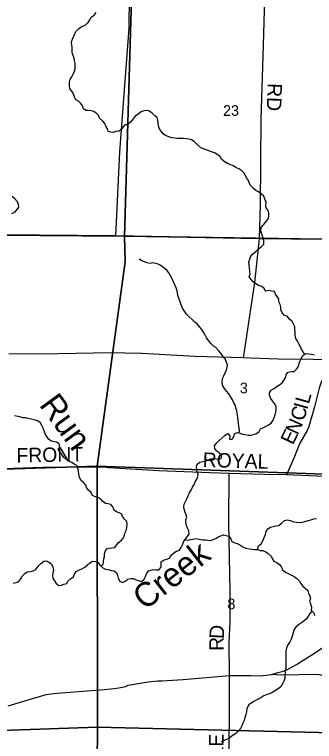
# Model space of a CAD drawing. Extents: x 1759416 to 2214760, y 252598 to 1116833.
# Drawn here: x 2035892 to 2042108, y 831751 to 846836 of the extents above; entities that cross this region are included whole.
import ezdxf

# ---------------------------------------------------------------- set-up
doc = ezdxf.new("R2010")
doc.units = 0
for name, color, linetype in [('GM_X_County_Road', 7, 'Continuous'), ('GM_X_County_Road_Text', 7, 'Continuous'), ('GM_X_Minor_River', 7, 'Continuous'), ('GM_X_Minor_River_Text', 7, 'Continuous'), ('GM_X_Section', 7, 'Continuous'), ('GM_X_Section_Text', 7, 'Continuous'), ('GM_X_State_Route', 7, 'Continuous'), ('GM_X_Township', 7, 'Continuous'), ('GM_X_Township_Road', 7, 'Continuous'), ('GM_X_Township_Road_Text', 7, 'Continuous'), ('GM_X_Township_ROW', 7, 'Continuous')]:
    doc.layers.add(name, color=color, linetype=linetype)

msp = doc.modelspace()

# ---------------------------------------------------------------- linework, layer by layer
at = {"layer": 'GM_X_County_Road'}
for points in [[(2035773, 839796), (2036812, 839804), (2037880, 839820), (2038178, 839819), (2038532, 839807), (2039632, 839744), (2040631, 839717), (2040780, 839712), (2041356, 839693), (2042079, 839682), (2042560, 839669)], [(2042560, 839669), (2042480, 839548), (2042386, 839417), (2042280, 839272), (2042262, 839237), (2042239, 839189), (2042207, 839081), (2042107, 838698), (2041989, 838286), (2041960, 838202), (2041808, 837938), (2041679, 837632), (2041529, 837281)], [(2042318, 837251), (2041529, 837281), (2041070, 837290), (2040343, 837310), (2039948, 837326), (2038873, 837370), (2038302, 837405), (2037837, 837432), (2037729, 837442), (2037640, 837441), (2036480, 837435), (2035666, 837406), (2035023, 837388), (2034952, 837385), (2034585, 837365), (2033664, 837333), (2032725, 837277), (2031577, 837259), (2030353, 837252), (2029288, 837232), (2028867, 837251)], [(2045101, 831738), (2045030, 831804), (2044987, 831837), (2044935, 831862), (2044809, 831917), (2044712, 831960), (2044609, 832018), (2044458, 832110), (2044057, 832365), (2043797, 832524), (2043653, 832621), (2043472, 832759), (2043345, 832860), (2043298, 832894), (2043246, 832918), (2043162, 832931), (2042976, 832944), (2042685, 832984), (2042557, 833027), (2042384, 833078), (2042267, 833121), (2042182, 833138), (2041399, 833124), (2041217, 833138)]]:
    msp.add_lwpolyline(points, dxfattribs=at)
at = {"layer": 'GM_X_Minor_River'}
for points in [[(2038230, 844549), (2038175, 844546), (2038144, 844508), (2038110, 844458), (2038058, 844419), (2037994, 844411), (2037936, 844391), (2037886, 844395), (2037836, 844407), (2037822, 844463), (2037782, 844522), (2037766, 844572), (2037720, 844626), (2037656, 844688), (2037632, 844740), (2037587, 844790), (2037535, 844822), (2037477, 844838), (2037423, 844842), (2037373, 844846), (2037323, 844882), (2037299, 844940), (2037269, 844990), (2037217, 845038), (2037153, 845075), (2037137, 845129), (2037111, 845189), (2037081, 845243), (2037036, 845293), (2037028, 845351), (2037030, 845433), (2037042, 845486), (2037080, 845546), (2037108, 845598), (2037134, 845658), (2037150, 845712), (2037152, 845771), (2037146, 845827), (2037134, 845883), (2037128, 845933), (2037106, 845987), (2037087, 846043), (2037089, 846099), (2037085, 846152), (2037077, 846202), (2037075, 846268), (2037093, 846326), (2037119, 846388), (2037143, 846438), (2037171, 846491), (2037227, 846543), (2037291, 846593), (2037347, 846611), (2037415, 846671), (2037455, 846723), (2037483, 846780), (2037543, 846826), (2037587, 846876)], [(2039021, 844323), (2038970, 844361), (2038924, 844423), (2038892, 844475), (2038876, 844529), (2038868, 844579), (2038859, 844644), (2038849, 844696), (2038797, 844736), (2038745, 844790), (2038673, 844836), (2038614, 844844), (2038552, 844834), (2038500, 844808), (2038446, 844762), (2038394, 844725), (2038350, 844669), (2038296, 844605), (2038236, 844551), (2038230, 844549)], [(2041900, 839782), (2041872, 839837), (2041838, 839889), (2041818, 839943), (2041788, 840005), (2041756, 840059), (2041726, 840115), (2041707, 840184), (2041707, 840248), (2041705, 840298), (2041701, 840354), (2041677, 840408), (2041647, 840466), (2041594, 840516), (2041542, 840574), (2041488, 840594), (2041440, 840647), (2041414, 840707), (2041414, 840765), (2041397, 840819), (2041371, 840873), (2041371, 840933), (2041335, 840983), (2041301, 841035), (2041279, 841089), (2041216, 841097), (2041160, 841106), (2041098, 841094), (2041068, 841148), (2041016, 841192), (2040951, 841214), (2040895, 841246), (2040839, 841286), (2040795, 841338), (2040757, 841395), (2040775, 841449), (2040770, 841507), (2040760, 841573), (2040758, 841639), (2040750, 841705), (2040768, 841757), (2040784, 841809), (2040832, 841867), (2040892, 841917), (2040948, 841973), (2041002, 842013), (2041056, 842069), (2041062, 842125), (2041050, 842187), (2041034, 842237), (2041014, 842299), (2041000, 842349), (2041005, 842415), (2041055, 842473), (2041099, 842531), (2041149, 842591), (2041165, 842649), (2041165, 842711), (2041147, 842767), (2041109, 842825), (2041099, 842887), (2041105, 842943), (2041079, 843007), (2041056, 843064), (2041006, 843116), (2040948, 843154), (2040894, 843188), (2040839, 843230), (2040791, 843284), (2040755, 843344), (2040739, 843394), (2040703, 843449), (2040656, 843535), (2040600, 843595), (2040542, 843633), (2040482, 843659), (2040421, 843697), (2040363, 843724), (2040303, 843746), (2040235, 843784), (2040183, 843838), (2040144, 843898), (2040092, 843930), (2040036, 843966), (2039974, 843987), (2039916, 844009), (2039865, 844031), (2039811, 844047), (2039753, 844073), (2039671, 844147), (2039618, 844204), (2039560, 844236), (2039506, 844248), (2039452, 844258), (2039392, 844262), (2039341, 844264), (2039269, 844262), (2039215, 844268), (2039153, 844275), (2039087, 844297), (2039021, 844323)], [(2035839, 842709), (2035899, 842733), (2035947, 842787), (2035981, 842837), (2035977, 842897), (2035953, 842949), (2035897, 843009), (2035845, 843060)], [(2040547, 838153), (2040554, 838206), (2040538, 838296), (2040531, 838356), (2040527, 838406), (2040517, 838481), (2040509, 838561), (2040501, 838619), (2040481, 838671), (2040471, 838721), (2040440, 838781), (2040412, 838843), (2040368, 838913), (2040334, 838963), (2040288, 839017), (2040245, 839078), (2040203, 839142), (2040195, 839210), (2040205, 839282), (2040227, 839342), (2040255, 839402), (2040287, 839464), (2040299, 839518), (2040303, 839568), (2040287, 839618), (2040256, 839688), (2040208, 839750), (2040168, 839812), (2040120, 839867), (2040067, 839929), (2040015, 839957), (2039963, 840011), (2039917, 840063), (2039874, 840127), (2039840, 840181), (2039806, 840242), (2039776, 840302), (2039726, 840358), (2039679, 840418), (2039627, 840454), (2039575, 840508), (2039513, 840566), (2039454, 840621), (2039416, 840679), (2039372, 840741), (2039346, 840815), (2039318, 840895), (2039285, 840983), (2039271, 841051), (2039263, 841105), (2039239, 841166), (2039213, 841224), (2039187, 841288), (2039156, 841350), (2039122, 841412), (2039092, 841474), (2039048, 841532), (2038989, 841582), (2038925, 841627), (2038869, 841653), (2038815, 841673), (2038757, 841681), (2038702, 841673), (2038642, 841683), (2038528, 841722), (2038478, 841758)], [(2041237, 838821), (2041204, 838871), (2041176, 838934), (2041176, 838984), (2041210, 839038), (2041262, 839068), (2041330, 839117), (2041382, 839155), (2041438, 839193), (2041484, 839257), (2041514, 839311), (2041522, 839363), (2041562, 839415), (2041633, 839431), (2041685, 839431), (2041739, 839475), (2041779, 839535), (2041793, 839601), (2041811, 839653), (2041837, 839705), (2041861, 839757), (2041925, 839799), (2041983, 839795), (2042049, 839791), (2042109, 839776)], [(2038243, 835121), (2038303, 835136), (2038355, 835132), (2038415, 835106), (2038475, 835086), (2038526, 835074), (2038578, 835116), (2038608, 835174), (2038628, 835232), (2038666, 835290), (2038770, 835318), (2038822, 835310), (2038882, 835311), (2038930, 835367), (2038934, 835417), (2038934, 835479), (2038992, 835517), (2039048, 835535), (2039102, 835555), (2039140, 835615), (2039196, 835665), (2039249, 835699), (2039309, 835723), (2039349, 835775), (2039371, 835835), (2039393, 835891), (2039431, 835945), (2039467, 835997), (2039509, 836055), (2039506, 836121), (2039478, 836175), (2039454, 836233), (2039444, 836299), (2039442, 836351), (2039464, 836403), (2039446, 836453), (2039432, 836503), (2039405, 836569), (2039399, 836623), (2039409, 836677), (2039435, 836731), (2039467, 836799), (2039493, 836853), (2039521, 836911), (2039559, 836977), (2039579, 837029), (2039615, 837085), (2039635, 837137), (2039671, 837195), (2039693, 837249), (2039695, 837303), (2039673, 837353), (2039673, 837403), (2039661, 837453), (2039679, 837507), (2039733, 837547), (2039795, 837559), (2039853, 837567), (2039907, 837595), (2039959, 837615), (2040019, 837621), (2040071, 837619), (2040124, 837611), (2040178, 837625), (2040188, 837677), (2040145, 837727), (2040081, 837781), (2040047, 837833), (2040039, 837885), (2040085, 837945), (2040135, 837999), (2040199, 838049), (2040261, 838109), (2040315, 838143), (2040353, 838091), (2040347, 838025), (2040398, 838020), (2040438, 838076), (2040450, 838136), (2040506, 838162), (2040566, 838148), (2040618, 838128), (2040674, 838118), (2040738, 838108), (2040789, 838110), (2040847, 838120), (2040909, 838143), (2040961, 838185), (2040991, 838237), (2041053, 838269), (2041105, 838291), (2041157, 838323), (2041209, 838353), (2041253, 838417), (2041277, 838477), (2041295, 838529), (2041309, 838585), (2041315, 838645), (2041317, 838699), (2041283, 838763), (2041237, 838821)], [(2037678, 835395), (2037728, 835426), (2037734, 835476), (2037744, 835538), (2037754, 835590), (2037754, 835646), (2037768, 835696), (2037802, 835751), (2037852, 835765), (2037912, 835767), (2037968, 835773), (2038006, 835825), (2038042, 835875), (2038100, 835921), (2038148, 835980), (2038168, 836030), (2038184, 836088), (2038212, 836144), (2038218, 836200), (2038226, 836258), (2038217, 836315), (2038173, 836365), (2038131, 836419), (2038115, 836469), (2038061, 836495), (2038005, 836519), (2037953, 836559), (2037933, 836611), (2037887, 836669), (2037827, 836679), (2037775, 836689), (2037723, 836731), (2037672, 836787), (2037620, 836813), (2037552, 836837), (2037502, 836863), (2037478, 836916), (2037422, 836964), (2037384, 837018), (2037370, 837068), (2037324, 837124), (2037272, 837170), (2037236, 837230), (2037223, 837298), (2037217, 837361), (2037207, 837421), (2037181, 837475), (2037129, 837503), (2037079, 837541), (2037017, 837571), (2036967, 837605), (2036911, 837643), (2036875, 837703), (2036836, 837757), (2036798, 837809), (2036832, 837864), (2036820, 837926), (2036762, 837964), (2036712, 837970), (2036656, 837980), (2036604, 838014), (2036558, 838078), (2036526, 838132), (2036508, 838200), (2036484, 838254), (2036461, 838311), (2036421, 838373), (2036367, 838403), (2036299, 838427), (2036239, 838441), (2036175, 838453), (2036125, 838467), (2036061, 838469), (2036001, 838491), (2035889, 838511)], [(2040929, 835732), (2040947, 835808), (2041007, 835855), (2041039, 835915), (2041065, 835981), (2041091, 836045), (2041111, 836105), (2041141, 836161), (2041197, 836197), (2041255, 836211), (2041311, 836225), (2041369, 836235), (2041427, 836281), (2041488, 836335), (2041546, 836349), (2041610, 836337), (2041674, 836312), (2041736, 836300), (2041794, 836298), (2041853, 836302), (2041911, 836318), (2041975, 836334), (2042035, 836348), (2042095, 836370), (2042151, 836378)], [(2039428, 835940), (2039483, 835931), (2039537, 835943), (2039597, 835952), (2039655, 835960), (2039721, 835950), (2039786, 835938), (2039850, 835934), (2039902, 835928), (2039954, 835924), (2040008, 835944), (2040062, 835965), (2040114, 835999), (2040168, 836015), (2040221, 836037), (2040277, 836025), (2040333, 836011), (2040373, 835955), (2040397, 835901), (2040455, 835875), (2040506, 835860), (2040564, 835832), (2040624, 835790), (2040686, 835760), (2040761, 835752), (2040813, 835740), (2040867, 835734), (2040931, 835732), (2040985, 835715), (2041041, 835717), (2041098, 835689), (2041150, 835653), (2041210, 835599), (2041232, 835547), (2041266, 835495), (2041329, 835465), (2041383, 835426), (2041425, 835370), (2041445, 835312), (2041511, 835266), (2041566, 835238), (2041636, 835200), (2041690, 835176), (2041746, 835135), (2041800, 835081), (2041823, 835029), (2041859, 834979), (2041917, 834935), (2041969, 834881), (2041987, 834827), (2042010, 834769), (2042024, 834719), (2042006, 834663), (2042024, 834606), (2042044, 834538), (2042042, 834478), (2042096, 834420), (2042109, 834366)], [(2035862, 835037), (2035924, 835051), (2035978, 835073), (2036030, 835137), (2036056, 835188), (2036102, 835240), (2036154, 835268), (2036220, 835276), (2036280, 835292), (2036332, 835320), (2036384, 835386), (2036440, 835443), (2036500, 835495), (2036550, 835501), (2036604, 835473), (2036656, 835435), (2036686, 835367), (2036696, 835316), (2036686, 835254), (2036676, 835194), (2036688, 835138), (2036722, 835084), (2036754, 835028), (2036808, 834990), (2036864, 834998), (2036916, 835018), (2036979, 835028), (2036998, 835080), (2037062, 835134), (2037116, 835170), (2037136, 835223), (2037170, 835275), (2037238, 835313), (2037298, 835341), (2037350, 835365), (2037402, 835417), (2037454, 835459), (2037510, 835492), (2037570, 835484), (2037624, 835462), (2037660, 835412), (2037723, 835353), (2037777, 835325), (2037831, 835319), (2037895, 835301), (2037951, 835293), (2038003, 835259), (2038023, 835197), (2038037, 835139), (2038075, 835079), (2038133, 835051), (2038199, 835087), (2038217, 835101), (2038243, 835121)], [(2042058, 834461), (2042010, 834410), (2041976, 834348), (2041946, 834294), (2041890, 834248), (2041838, 834211), (2041778, 834173), (2041726, 834121), (2041684, 834065), (2041666, 834007), (2041644, 833933), (2041628, 833877), (2041600, 833817), (2041556, 833757), (2041526, 833695), (2041514, 833625), (2041512, 833575), (2041516, 833511), (2041516, 833443), (2041513, 833367), (2041513, 833303), (2041509, 833250), (2041503, 833178), (2041497, 833122), (2041495, 833064), (2041473, 833004), (2041449, 832948), (2041411, 832886), (2041357, 832840), (2041303, 832809), (2041245, 832777), (2041189, 832749), (2041129, 832725), (2041062, 832697), (2040994, 832659), (2040912, 832617), (2040852, 832581), (2040798, 832549), (2040746, 832512), (2040708, 832432), (2040700, 832368), (2040686, 832311), (2040668, 832247), (2040650, 832187), (2040626, 832131), (2040606, 832077), (2040578, 832022), (2040528, 831966), (2040472, 831912), (2040406, 831868), (2040346, 831818), (2040286, 831794), (2040228, 831770), (2040172, 831742)]]:
    msp.add_lwpolyline(points, dxfattribs=at)
at = {"layer": 'GM_X_Section'}
for points in [[(2038329, 847644), (2038174, 842236), (2032915, 842279), (2033089, 847791)], [(2043778, 847589), (2043627, 842153), (2038174, 842236), (2038329, 847644)], [(2038174, 842236), (2038184, 841701), (2037606, 837464), (2032235, 837288), (2032915, 842279)], [(2043627, 842153), (2043306, 837262), (2037606, 837464), (2038184, 841701), (2038174, 842236)], [(2032235, 837288), (2037606, 837464), (2037612, 832048), (2032216, 831858)], [(2043306, 837262), (2043059, 831915), (2037612, 832048), (2037606, 837464)], [(2037612, 832048), (2037563, 826696), (2032212, 826573), (2032216, 831858)], [(2043059, 831915), (2043000, 826559), (2037563, 826696), (2037612, 832048)]]:
    msp.add_lwpolyline(points, close=True, dxfattribs=at)
at = {"layer": 'GM_X_State_Route'}
msp.add_lwpolyline([(2035761, 832494), (2036549, 832724), (2036702, 832748), (2036773, 832755), (2037484, 832806), (2037755, 832831), (2037951, 832850), (2038057, 832865), (2038195, 832895), (2038244, 832916), (2038536, 832971), (2038663, 832988), (2038861, 833008), (2038943, 833011), (2039387, 833039), (2040347, 833121), (2040792, 833119), (2040992, 833115), (2041217, 833138), (2041356, 833181), (2041442, 833206), (2041535, 833241), (2041735, 833349), (2042051, 833548), (2042460, 833818)], dxfattribs=at)
at = {"layer": 'GM_X_Township'}
for points in [[(2043642, 842159), (2040965, 842190), (2037988, 842245), (2035607, 842262), (2030332, 842322), (2028942, 842357), (2028943, 842500), (2028952, 842930), (2029018, 847875), (2029029, 848523), (2029046, 849495), (2029046, 849735), (2029030, 849829), (2029030, 849879), (2029053, 849934), (2029103, 853671), (2029128, 855177), (2029345, 867783)], [(2028807, 831533), (2028809, 831909), (2028803, 832220), (2028798, 832529), (2028805, 832839), (2028816, 833356), (2028833, 833954), (2028838, 834843), (2028867, 837251), (2028902, 839762), (2028942, 842357), (2030332, 842322), (2035607, 842262), (2037988, 842245), (2040965, 842190), (2043642, 842159), (2049021, 842051), (2053716, 841956), (2054399, 841942), (2054222, 838243), (2054175, 836924), (2054096, 834376), (2053974, 831534)]]:
    msp.add_lwpolyline(points, dxfattribs=at)
at = {"layer": 'GM_X_Township_Road'}
for points in [[(2041048, 849930), (2041057, 849568), (2041072, 848606), (2041082, 847409), (2041047, 846203), (2040994, 844666), (2040982, 842877), (2040965, 842190), (2040951, 842057)], [(2040951, 842057), (2040864, 841275), (2040637, 839757), (2040631, 839717)], [(2040289, 827778), (2040300, 828075), (2040306, 828776), (2040315, 829755), (2040324, 830925), (2040347, 832230), (2040347, 833121), (2040344, 833802), (2040362, 834236), (2040361, 834869), (2040333, 836285), (2040343, 837310)]]:
    msp.add_lwpolyline(points, dxfattribs=at)
at = {"layer": 'GM_X_Township_ROW'}
msp.add_lwpolyline([(2038448, 850310), (2038423, 849750), (2038281, 848597), (2038262, 846556), (2038067, 843990), (2037988, 842245)], dxfattribs=at)

# ---------------------------------------------------------------- texts
at = {"layer": 'GM_X_County_Road_Text'}
for s, rotation, p in [('L', 74.2194, (2041991, 838740)), ('I', 74.2272, (2041958, 838621)), ('C', 74.171, (2041890, 838384)), ('N', 65.1507, (2041761, 838096)), ('E', 64.4699, (2041663, 837890)), ('FRONT', 1.0492, (2035934, 837539)), ('ROYAL', 358.217, (2039789, 837450))]:
    msp.add_text(s, height=300, rotation=rotation, dxfattribs=at).set_placement(p)
at = {"layer": 'GM_X_Minor_River_Text'}
for s, rotation, p in [('Run', 306.1545, (2036389, 838734)), ('Creek', 38.0576, (2038592, 834459))]:
    msp.add_text(s, height=500, rotation=rotation, dxfattribs=at).set_placement(p)
at = {"layer": 'GM_X_Section_Text'}
for s, p in [('23', (2040215, 844734)), ('3', (2040562, 838976)), ('8', (2040305, 834495))]:
    msp.add_text(s, height=221, rotation=0, dxfattribs=at).set_placement(p)
at = {"layer": 'GM_X_Township_Road_Text'}
for s, rotation, p in [('RD', 268.0262, (2041138, 845416)), ('D', 87.3326, (2040229, 833874)), ('R', 89.9297, (2040229, 833631)), ('WINKLE', 89.303, (2040207, 830371))]:
    msp.add_text(s, height=300, rotation=rotation, dxfattribs=at).set_placement(p)

doc.saveas('drawing.dxf')
